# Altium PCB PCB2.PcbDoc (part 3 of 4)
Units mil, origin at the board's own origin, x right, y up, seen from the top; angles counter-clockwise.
Board outline 3980.79 x 2126 mil, 6 copper layers (Top Layer, Signal Layer 1, Signal Layer 2, Signal Layer 3, Signal Layer 4, Bottom Layer), stack 61.485 mil thick; 358 components, 190 nets, 1000 pads, 509 vias.
Unrouted connection lines stored in the file: 83.
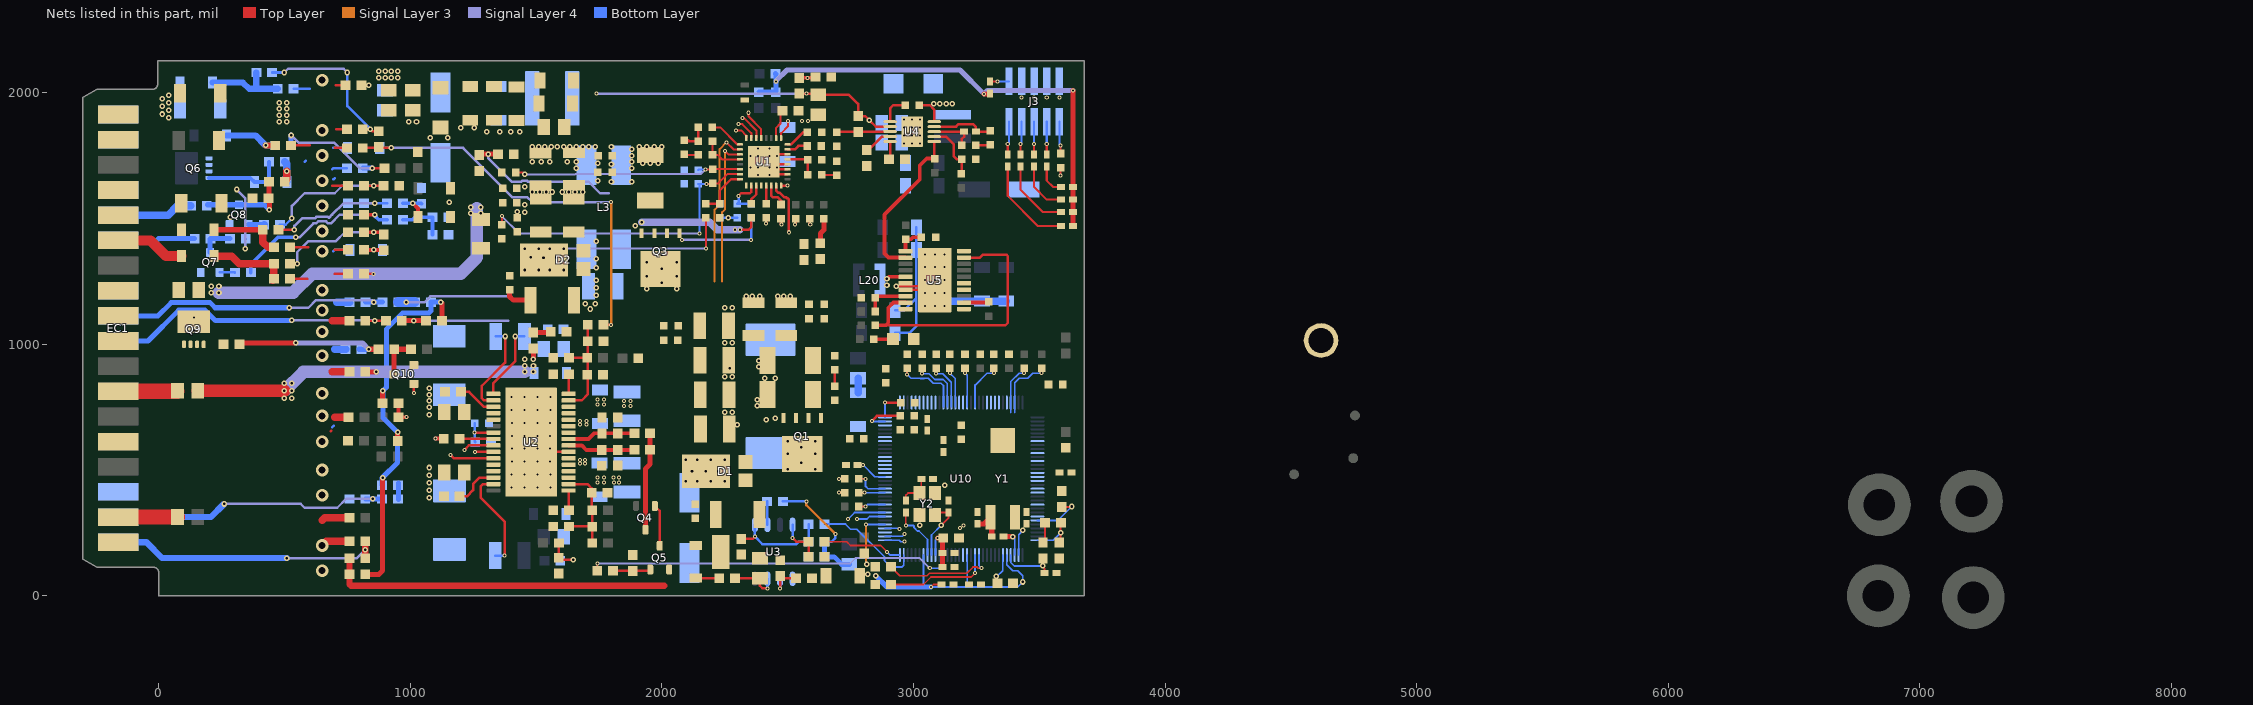
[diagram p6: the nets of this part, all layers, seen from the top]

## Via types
v1: diameter 22, hole 10, Top Layer to Bottom Layer, tented both sides, 287 vias
v2: diameter 16, hole 8, Top Layer to Bottom Layer, tented both sides, 129 vias
v3: diameter 19.68, hole 7.87, Top Layer to Bottom Layer, 47 vias
v4: diameter 19.68, hole 7.87, Top Layer to Bottom Layer, tented both sides, 28 vias
v5: diameter 50, hole 28, Top Layer to Bottom Layer, 18 vias

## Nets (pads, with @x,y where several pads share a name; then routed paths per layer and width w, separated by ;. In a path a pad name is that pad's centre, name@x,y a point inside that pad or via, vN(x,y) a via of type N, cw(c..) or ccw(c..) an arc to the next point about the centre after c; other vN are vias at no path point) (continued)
GND: C2.1 C3.1 C4.2 C5.2 C6.2 C7.2 C8.2 C9.2 C10.1 C11.2 C12.1 C13.1 C14.2 C15.1 C16.2 C17.2 C19.1 C20.2 C21.2 C22.2 C23.2 C24.2 C25.2 C26.2 C27.2 C28.2 C29.2 C31.2 C32.2 C34.1 C35.2 C36.2 C37.1 C38.1 C39.1 C40.2 C41.2 C42.2 C43.1 C44.2 C45.2 C46.2 C47.2 C48.2 C49.2 C51.2 C52.1 C53.1 C54.1 C55.2 C56.2 C57.2 C58.2 C59.2 C61.1 C62.2 C63.1 C64.2 C65.2 C66.2 C67.1 C68.2 C69.2 C70.2 C71.2 C72.2 C73.2 C74.2 C75.2 C76.2 C77.2 C78.2 C79.2 C80.2 C81.1 C82.2 C83.2 C85.2 C86.2 C87.2 C88.2 C89.2 C90.2 C92.2 C93.2 C94.2 C95.2 C96.2 C97.2 C98.2 C99.2 C100.2 C101.2 C102.2 C103.2 C104.2 C105.2 C106.2 C107.2 C108.2 C109.2 C110.2 C111.2 C112.2 C113.2 C114.2 C115.2 C116.2 C117.2 C118.2 C119.2 C120.2 C121.2 C122.2 C123.2 C124.2 C125.2 C126.2 C127.2 C128.2 C129.2 C130.2 C131.2 C132.2 C133.2 C134.2 D3.2 D4.2 D5.1 D8.2 D9.2 D10.2 D11.2 D15.2 D16.2 EC1.3 EC1.4 EC1.7 EC1.8 EC1.19 EC1.27 EC1.32 EC1.35 J3.3 J3.5 J3.7 J3.9 L3.2 Q5.2 Q7.2 Q8.2 Q9.1 Q9.2 Q9.3 Q10.2 R6.1 R7.1 R9.1 R10.1 R13.1 R23.1 R24.1 R29.1 R31.1 R32.1 R37.1 R39.1 R41.1 R47.1 R50.1 R53.1 R57.1 R58.1 R59.1 R60.1 R72.1 R76.1 R77.1 R78.1 R98.2 R101.2 R115.1 R116.1 R117.1 R118.1 RT1.1 TP3.1 U1.17 U1.20 U1.24 U1.26 U1.27 U1.28 U1.30 U1.33 U2.3 U2.4 U2.7 U2.10 U2.13 U2.14 U2.33@1480.2,610.59 U3.5 U4.9 U4.11@2995,1845 U5.6 U5.7 U5.10 U5.11 U5.14 U5.15 U5.20 U5.21@3085,1255 U10.10 U10.17 U10.48 U10.55 U10.58 U10.80 U10.114 Y1.3 Y2.2 Y2.4 | length 3402.6
  Top Layer w10: R59.1@521.5,1260 590,1260 ; R117.1@525,1385 595,1385 ; R115.1@526.5,1790 600,1790 ; 685,655 686.61,656.61 ; 690,1630 C49.2@753.5,1630 ; 700,1280 C134.2@753.5,1280 ; 700,1375 R60.1@753.5,1375 ; 700,1780 R58.1@748.5,1780 ; 705,2030 C68.2@743.5,2030 ; 705.35,1855 C17.2@748.5,1855 ; U2.33@1480.2,610.59 1539.41,610.59 1577.8,572.2 U2.7@1629.8,572.2 ; C41.2@2088.5,1810.24 2104.2,1810.24 2107.2,1807.24 C40.2@2145.5,1807.24 2145.5,1860.82 R24.1@2144.08,1862.24 ; U1.33@2405,1725 v3(2427.24,1747.24) 2434.53,1754.53 U1.30@2499.49,1754.53 ; U1.33@2414.84,1715.16 U1.28@2499.49,1715.16 ; v2@2416,1481 C39.1@2416,1503 ; U1.33@2434.53,1695.47 U1.27@2499.49,1695.47 ; U1.33@2454.21,1675.79 U1.26@2499.49,1675.79 ; U1.24@2473.9,1630.51 2499.49,1630.51 v2(2500,1630) ; v2(2530,1475) 2531.76,1476.76 C13.1@2531.76,1499.24 ; v2@2587.76,1477.24 R10.1@2587.76,1499.24 ; v1(2931.46,1230) U5.21@3060,1230 ; U5.7@2968.86,1216.61 3046.61,1216.61 U5.21@3060,1230 ; U4.9@3082.6,1864.69 3169.69,1864.69 3180,1875 3236.65,1875 3248.62,1863.03 C102.2@3248.62,1845 3302,1845 C104.2@3305,1848 ; v3(3085,1255) U5.21@3060,1230
  Top Layer w30: v5(650,200) 666.85,216.85 C88.2@758.5,216.85 ; 650,300 660,310 C133.2@758.5,310 ; 690,890 C86.2@758.5,890 ; 690.47,1093.7 C85.2@758.5,1093.7 ; 700,710 C57.2@755,710
  Bottom Layer w10: R57.1@536.5,2015 600,2015 ; 580,1725 585,1730 ; 690,670 695.31,675.31 ; 690,1695 695,1700 C31.2@748.5,1700 ; 695,1370 700,1375 D9.2@760.53,1375 ; 695,1655 699.43,1659.43 ; 695,1780 D8.2@749.96,1780 ; C34.1@2230,1502 C37.1@2300,1502 ; C95.2@2926.93,1045 2985,1045 3011.93,1071.93 3011.93,1183.8 ; C94.2@2926.93,1135 2963.13,1135 3011.93,1183.8 ; C89.2@3011.93,1465 C90.2@3011.93,1375 3011.93,1183.8
  Bottom Layer w30: 700,980 C66.2@743.5,980 ; 707.27,1167.27 C74.2@759.5,1167.27 ; v4(3124.37,1152.64) 3143.13,1171.39 C100.2@3273.21,1171.39 C101.2@3369.21,1171.39
  other v1: 3025,280 3125,440 2300,680 2250,730 2280,730 2380,755 2380,780 2410,865 2450,865 2250,870 2280,870 2270,905 2385,910 2385,935 2250,1005 2280,1005 2250,1145 2280,1145 2265,1502 285,1505 1455,1525 1425,1527.17 1455,1555 1155,1565 1485,1605 1515,1605 1540,1605 1565,1605 1605,1605 1630,1605 1655,1605 1685,1605 1455,1625 1800,1645 1880,1645 1880,1700 1800,1715 1925,1720 1955,1720 1985,1720 1880,1725 1880,1750 1880,1775 1800,1784.53 1910,1785 1940,1785 1970,1785 2000,1785 1080,1820 1150,1820 1435.46,1843.92 1305,1845 1355,1845 1400,1845 1200,1860 1255,1860 995,1885 1025,1885
  other v2: 3185,270 3200,280 1745,450 1770,450 1810,450 1830,450 1745,470 1770,470 1808.87,469.77 1830,470 1850,755 1875,755 1745,760 1770,760 1850,775 1875,775 1745,780 1770,780 2590,1475 2415,1480 3430,1980 3480,1980 3530,1980 3580,1980
  other v3: 1405.39,533.82 1454.61,533.82 1505.79,533.82 1555,533.82 1405.39,585 1454.61,585 1505.79,585 1555,585 1405.39,636.18 1454.61,636.18 1505.79,636.18 1555,636.18 1405.39,687.36 1454.61,687.36 1505.79,687.36 1555,687.36 3045.63,1203.82 3085,1203.82 3124.37,1203.82 3045.63,1255 3124.37,1255 3045.63,1306.18 3085,1306.18 3124.37,1306.18 2382.76,1671.85 2427.24,1671.85 2351.85,1702.76 2382.76,1702.76 2427.24,1702.76 2458.15,1702.76 2351.85,1747.24 2382.76,1747.24 2458.15,1747.24 2382.76,1778.15 2427.24,1778.15 2963.5,1829.25 2995,1829.25 3026.5,1829.25 2963.5,1860.75 2995,1860.75 3026.5,1860.75
  other v4: 1403.43,431.46 1454.61,431.46 1505.79,431.46 1556.97,431.46 1403.43,482.64 1454.61,482.64 1505.79,482.64 1556.97,482.64 1403.43,738.54 1454.61,738.54 1505.79,738.54 1556.97,738.54 1403.43,789.72 1454.61,789.72 1505.79,789.72 1556.97,789.72 3045.63,1152.64 3085,1152.64 3045.63,1357.36 3085,1357.36 3124.37,1357.36 2963.5,1797.76 2995,1797.76 3026.5,1797.76 2963.5,1892.24 2995,1892.24 3026.5,1892.24
  other v5: 650,100 650,400 650,500 650,612.99 650,715 650,805 650,955 650,1050 650,1135 650,1215 650,1370 650,1450 650,1550 650,1650 650,1750 650,1850 650,2050
HB: D7.2 EC1.11 | length 276.9
  Top Layer w40: EC1.11@-160.24,1412.99 -32.99,1412.99 30,1350 D7.2@90.53,1350
HB_DRIVE_MICRO: Q10.1 U10.49 | length 37.9
  Top Layer w10: Q10.1@1014.37,842.6 v2(1014.37,805.63) v2@1015,805
HB_LED: EC1.17 Q9.5 Q9.6 Q9.7 Q9.8 Q9.9@140,1089.33
  other v3: 140,1055.08 140,1105.28
HB_MICRO: D9.1 R56.2 R60.2 U10.103 | length 229.7
  Top Layer w15: R60.2@816.5,1375 v1(855,1375) 893.5,1375 R56.2@895,1373.5
  Bottom Layer w7: v2(2775,305) 2815,305 2825.39,315.39 U10.103@2886.85,315.39
  Bottom Layer w15: v1(855,1375) D9.1@889.47,1375
JTAG_TCK: R82.1 R86.2 U10.100 | length 349.5
  Top Layer w8: R86.2@3425,1706.38 3425,1615 3515,1525 R82.1@3586.38,1525
  Bottom Layer w7: U10.100@2886.85,268.15 2941.85,268.15 v2(2945,265)
JTAG_TDI: R84.1 R88.2 U10.98 | length 204.7
  Top Layer w8: R88.2@3530,1706.38 3530,1650 3555,1625 R84.1@3586.38,1625
  Bottom Layer w7: U10.98@2886.85,236.65 2956.65,236.65 v2(2965,245)
JTAG_TDO: R83.1 R87.2 U10.97 | length 289.1
  Top Layer w8: R87.2@3480,1706.38 3480,1625 3530,1575 R83.1@3586.38,1575
  Bottom Layer w7: U10.97@2886.85,220.91 2944.09,220.91 2950,215 v2(2965,215)
JTAG_TMS: R81.1 R85.2 U10.99 | length 377.5
  Top Layer w8: R85.2@3375,1706.38 3375,1590 3495,1470 R81.1@3586.38,1470
LB1/LB2: D6.2 D19.2 D20.2 EC1.1 EC1.2
  other v1: 40,1900 15,1915 40,1930 15,1945 40,1960 15,1975 40,1990
LB_FAULT: EC1.10 R127.1 | length 304.1
  Bottom Layer w30: EC1.10@-160.24,1512.99 37.99,1512.99 75,1550 R127.1@128.5,1550
LB_FAULT_MICRO: R129.2 U10.5
LB_MICRO: D8.1 R28.1 R54.2 R58.2 U10.118 | length 1637.8
  Top Layer w10: R58.2@811.5,1780 R54.2@871.5,1780 ; R54.2@875,1783.5 878.5,1780 v1(925,1780) ; R28.1@1768.5,1076.77 v2(1798.23,1076.77)
  Signal Layer 3 w10: v2(1798.23,1076.77) v2(1798.23,1565)
  Signal Layer 4 w10: v1(925,1780) 1210,1780 1405,1585 1465,1585 1485,1565 v2(1798.23,1565)
  Bottom Layer w10: D8.1@878.9,1780 v1(925,1780)
LB_NTC: C124.1 R136.1 R139.2 U10.18 | length 626.3
  Top Layer w10: v2(3205,885) C124.1@3205,905
  Top Layer w20: R139.2@966.5,1093.7 v1(1015,1093.7) R136.1@1060.57,1093.7
  Signal Layer 4 w10: v1(1015,1093.7) 1388.7,1093.7
  Bottom Layer w7: v2(3205,885) 3213.62,876.38 U10.18@3213.62,750
LBHB+: C63.2 C64.1 C86.1 D4.1 L2.1 R40.2 R52.1 U2.17 | length 1718.9
  Top Layer w10: U2.17@1330.59,802.52 1330.59,845.59 1416.68,931.68 v1(1416.68,1030.77)
  Top Layer w20: C86.1@821.5,890 v1(865,890) ; v1(1489.52,940.48) R40.2@1489.52,983.5
  Top Layer w50: L2.1@155,815 v1(500,815)
  Signal Layer 4 w50: v1(500,815) 575,890 v1(1455,890)
  Bottom Layer w10: v1(1416.68,1030.77) R52.1@1454.09,1030.77
  other v1: 500,785 530,785 530,815 500,845 530,845 1490,890 1455,915 1490,915 1455,940
LBHB-: EC1.16
LBHB_NTC: C85.1 EC1.20 R139.1 | length 1169.9
  Top Layer w10: C85.1@821.5,1093.7 v1(860,1093.7) R139.1@903.5,1093.7
  Signal Layer 4 w10: v1(529.58,1094.58) 859.12,1094.58 v1(860,1093.7)
  Bottom Layer w20: EC1.20@-160.24,1012.99 -42.01,1012.99 80,1135 185,1135 225.42,1094.58 v1(529.58,1094.58)
LBHB_RBIN: C74.1 EC1.18 R138.1 | length 1128.7
  Signal Layer 4 w10: v1(520,1145) 595,1145 625,1175 848.27,1175 v1(856,1167.27)
  Bottom Layer w20: EC1.18@-160.24,1112.99 -2.01,1112.99 50,1165 205,1165 225,1145 v1(520,1145) ; C74.1@822.5,1167.27 v1(856,1167.27) R138.1@889.5,1167.27
LBHBPWM: R51.1 U10.44
LHI_1-2: C58.1 R47.2 U2.23 | length 150.2
  Top Layer w10: v2(1256.02,648.98) U2.23@1330.59,648.98
  Bottom Layer w10: R47.2@1257.2,685.59 1257.2,612.09 C58.1@1258.7,610.59
LIN_RXD: R64.1 U10.95 | length 437.3
  Bottom Layer w7: R64.1@2646.5,285 2730,285 2750,265 2775,265 2885,155 2885,140 2910,115 2955,115 2961.65,121.65 U10.95@2961.65,161.85
LIN_TXD: R100.1 U10.96 | length 321.4
  Top Layer w7: R100.1@2646.5,215 2735,215 2750,200 2870,200 v2(2895,175)
  Bottom Layer w7: v2(2895,175) 2908.15,161.85 U10.96@2945.91,161.85
MCU_3V3A: C109.1 C114.1 L23.2 U10.8 | length 58.1
  Bottom Layer w30: C114.1@2780,806.93 L23.2@2780,865
MCU_3V3D: C105.1 C106.1 C107.1 C108.1 C110.1 L22.2 R16.2 R17.2 R20.2 R61.2 R62.2 R66.1 R80.2 R81.2 R82.2 R83.2 R84.2 R93.2 R94.1 R96.1 R99.1 R102.2 R103.2 R105.2 R130.2 R131.2 R135.2 R136.2 R140.2 R141.2 U10.7 U10.16 U10.26 U10.28 U10.39 U10.47 U10.51 U10.52 U10.69 U10.79 U10.90 U10.101 U10.113 U10.122 | length 5435.9
  Top Layer w7: C105.1@2778.62,520 v2(2800,520) ; v2(3070,35) 3080,45 C108.1@3111.38,45
  Top Layer w20: R141.2@821.5,85 875,85 890.16,100.16 v1(890.16,470) ; R130.2@890,765 v1@890,813.5 ; R131.2@950,615.94 v1(950,649.45) ; v1(1122.27,1167.27) 1126.5,1163.04 R136.2@1126.5,1093.7 ; v2(3280,1995) R80.2@3303.62,1995 ; R81.2@3633.62,1470 R82.2@3633.62,1525 R83.2@3633.62,1575 R84.2@3633.62,1625 v2(3633.62,2008.62)
  Signal Layer 3 w7: v2(2811.1,283.9) 2811.1,128.9 v1(2815,125)
  Signal Layer 3 w10: v2(2575,375) 2575,360 v2(2690,245)
  Signal Layer 4 w20: v2(2453,2045) 2498,2090 3185,2090 v2(3280,1995) 3293.62,2008.62 v2(3633.62,2008.62)
  Bottom Layer w7: v2(2800,520) 2847.13,472.87 U10.113@2886.85,472.87 ; v2(2811.1,283.9) U10.101@2886.85,283.9 ; U10.90@3040.39,161.85 3040.39,45.39 3050.79,35 ; v2(3070,35) 3213.62,35 ; U10.79@3213.62,161.85 3213.62,35 ; U10.69@3371.1,161.85 3371.1,124.1 3395.2,100 3415,100 3435,80 v1(3435,55) 3415,35 3213.62,35
  Bottom Layer w10: R66.1@2481.5,375 v2(2575,375) ; R62.2@2646.5,215 2675,215 2690,230 v2(2690,245)
  Bottom Layer w20: R140.2@888.5,440 v1@888.5,468.35 ; v1(890.16,470) 950,529.84 v1(950,649.45) 891.5,707.95 v1(891.5,815) 905,828.5 905,1060 970,1125 1075,1125 1082.5,1132.5 R135.2@1082.5,1167.27 v1(1122.27,1167.27) ; R17.2@2386,2001.5 R16.2@2453,2001.5 v2(2453,2045) 2453,2073.5 R20.2@2451.5,2075 ; R62.2@2646.5,215 R61.2@2646.5,155 2685,155 2715,125 L22.2@2745,125 ; v1(2850,80) 2895,35 3050.79,35 v2(3070,35)
  other v1: 2818.98,86.46
MISOM: R93.1 U1.7 U2.26 U10.1 | length 158.7
  Top Layer w8: v2(2305,1875) 2320,1875 2355.79,1839.21 U1.7@2355.79,1819.49
  Top Layer w10: v2(1257.2,572.2) U2.26@1330.59,572.2
MOSIM: U1.8 U2.27 U10.2 | length 235.4
  Top Layer w8: v2(2295,1850) 2315,1850 2336.1,1828.9 U1.8@2336.1,1819.49
  Top Layer w10: v2(1160,560) 1173.39,546.61 U2.27@1330.59,546.61
NetC1_1: C1.1 R1.1
NetC12_2: C12.2 R4.1 U1.23 | length 280.3
  Top Layer w10: U1.23@2454.21,1630.51 2454.21,1610.79 2462.13,1602.87 2467.4,1602.87 2487.07,1583.2 2494.06,1583.2 2497.27,1580 2500,1580 2503.88,1576.12 2503.88,1446.12 v2(2505,1445) ; R4.1@2687,832.68 C12.2@2687,897.68
NetC14_1: C14.1 R12.2 | length 59.2
  Top Layer w8: R12.2@2636.2,1672.94 2694.06,1672.94 C14.1@2695,1672
NetC15_2: C15.2 R12.1 U1.29 | length 141.5
  Top Layer w10: U1.29@2499.49,1734.84 2578.3,1734.84 C15.2@2580.2,1732.94 R12.1@2580.2,1672.94
NetC16_1: C16.1 R11.2 R14.2 U1.1 | length 79.3
  Top Layer w8: U1.1@2473.9,1819.49 2473.9,1839.29 2501.85,1867.24 v2(2501.85,1887.24)
  other v2: 2556.85,1887.24 2581.85,1887.24
NetC17_1: C17.1 R44.2 R54.1 | length 640.8
  Top Layer w10: C17.1@811.5,1855 v1(841.46,1855) 849.96,1846.5 R54.1@875,1846.5
  Signal Layer 4 w10: v1(500,2080) 515,2095 735,2095 v1(750,2080)
  Bottom Layer w10: R44.2@451.5,2080 v1(500,2080) ; v1(750,2080) 750,1946.46 v1(841.46,1855)
NetC18_1: C18.1 R18.1 | length 116.6
  Top Layer w20: C18.1@1395,1217 1395,1190 1410,1175 R18.1@1478.39,1175
NetC18_2: C18.2 C25.1 C26.1 C27.1 D2.3 R19.1 R22.2 R26.2 | length 687
  Top Layer w8: v2(2175,1380) R22.2@2175,1502
  Signal Layer 4 w8: v1(1610,1380) v2(2175,1380)
  other v1: 1455,1295 1510,1295 1555,1295 1610,1295 1529.76,1343.76 1480,1345 1580,1345 1455,1380 1510,1380 1555,1380
NetC24_1: C24.1 R55.2 R56.1 | length 494.3
  Top Layer w10: R55.2@521.5,1320 v1(551.02,1320)
  Top Layer w15: C24.1@816.5,1445 v1(855,1445) 886.5,1445 R56.1@895,1436.5
  Signal Layer 4 w10: v1(551.02,1320) 551.02,1366.02 595,1410 705,1410 740,1445 v1(855,1445)
NetC30_1: C30.1 L3.3 Q3.5
  other v1: 1940,1220 2060,1220 2000,1245 1940,1270 2060,1270 2000,1300 1940,1325 2060,1325 2000,1355
NetC30_2: C30.2 D2.1 D2.2 L3.4 R18.2
  other v1: 1715,1140 1695,1160 1735,1160 1740,1195 1740,1225 1740,1255 1740,1304.22 1740,1340 1740,1410
NetC31_1: C31.1 R111.2 R112.1 | length 510.3
  Top Layer w10: v1(850,1700) R112.1@898.5,1700
  Signal Layer 4 w10: v1(526.5,1830.99) 557.49,1800 698.98,1800 798.98,1700 v1(850,1700)
  Signal Layer 4 w20: v1@526.5,1826.5 v1(526.5,1830.99)
  Bottom Layer w20: R111.2@526.5,1790 v1(526.5,1830.99) ; C31.1@811.5,1700 v1(850,1700)
NetC32_1: C32.1 R113.2 R114.1 | length 530.4
  Top Layer w10: R113.2@477.07,1455 v1(540,1455)
  Signal Layer 4 w10: v1(540,1455) 540,1470 570,1500 621.16,1500 626.91,1505.75 673.09,1505.75 676.92,1501.92 690,1515 735,1560 v1(860,1560)
  Bottom Layer w10: C32.1@816.5,1560 v1(860,1560) R114.1@908.5,1560
NetC33_1: C33.1 C35.1 R26.1 U1.15 | length 1228.9
  Top Layer w8: R26.1@1364.15,1475.76 v2(1364.15,1509.15) ; v2(2176.85,1637.24) 2199.85,1637.24 C33.1@2201.85,1639.24 2223.85,1639.24 2260.39,1675.79 U1.15@2310.51,1675.79
  Signal Layer 4 w8: v2(1364.15,1509.15) 1433.3,1440 v2(2150,1440)
  Bottom Layer w8: v2(2150,1440) 2150,1632.09 C35.1@2144.85,1637.24 v2(2176.85,1637.24)
NetC33_2: C33.2 C36.1 R27.1 U1.14 | length 932.1
  Top Layer w8: R27.1@1420.2,1682.44 1447.56,1682.44 v1(1455,1675) ; v2(2173.85,1695.24) C33.2@2201.85,1695.24 2202.08,1695.47 U1.14@2310.51,1695.47
  Signal Layer 4 w8: v1(1455,1675) 1655,1675 1657.13,1677.13 2155.73,1677.13 v2(2173.85,1695.24)
  Bottom Layer w8: C36.1@2144.85,1692.24 2147.85,1695.24 v2(2173.85,1695.24)
NetC34_2: C34.2 R22.1 R29.2 U1.16 | length 206.6
  Top Layer w10: R22.1@2175,1558 R29.2@2230,1558 2230,1610 2276.1,1656.1 U1.16@2310.51,1656.1
NetC37_2: C37.2 R30.1 U1.18 | length 171.1
  Top Layer w10: v2(2305,1590) 2315,1600 2350,1600 2355.79,1605.79 U1.18@2355.79,1630.51
  Bottom Layer w10: v2(2305,1590) 2305,1563 C37.2@2300,1558 R30.1@2355,1558
NetC39_2: C39.2 U1.21 | length 72
  Top Layer w10: U1.21@2414.84,1630.51 2414.84,1560.16 C39.2@2416,1559
NetC40_1: C40.1 R33.2 U1.12 | length 171.2
  Top Layer w8: C40.1@2201.5,1807.24 R33.2@2201.5,1752.24 2221.85,1752.24 2239.25,1734.84 U1.12@2310.51,1734.84
NetC41_1: C41.1 R33.1 | length 57.8
  Top Layer w8: C41.1@2088.5,1754.24 2090.5,1752.24 R33.1@2145.5,1752.24
NetC42_1: C42.1 R123.2 R124.1 | length 717
  Top Layer w15: C42.1@816.5,1515 v1(860,1515)
  Signal Layer 4 w10: v1(545,1425) 560,1425 615,1480 626.44,1480 634.31,1487.87 665.69,1487.87 673.56,1480 685,1480 720,1515 v1(860,1515)
  Bottom Layer w15: R123.2@366.5,1285 366.5,1316.5 475,1425 v1(545,1425) ; v1(860,1515) 860,1510 875,1495 R124.1@908.5,1495
NetC45_1: C45.1 R124.2 R125.1 | length 191.2
  Bottom Layer w15: R124.2@971.5,1495 1008.95,1495 1018.95,1505 C45.1@1088.5,1505 R125.1@1088.5,1435
NetC48_1: C48.1 U2.1 | length 78.9
  Top Layer w10: U2.1@1629.8,418.66 1629.8,342.48 C48.1@1631.69,340.59
NetC49_1: C49.1 R128.2 R129.1 | length 543.4
  Top Layer w10: C49.1@816.5,1630 v1(855,1630) R129.1@893.5,1630
  Signal Layer 4 w10: v1(530,1500) 530,1550 580,1600 700,1600 730,1630 v1(855,1630)
  Bottom Layer w10: R128.2@482.07,1475 505,1475 v1(530,1500)
NetC50_1: C50.1 L4.1 L5.2
  other v1: 1075,390 1075,420 1075,450 1075,480 1075,510
NetC50_2: C50.2 U2.30 | length 179.3
  Top Layer w10: C50.2@1196.69,395.59 1225.59,395.59 1250,420 1250,445 1274.84,469.84 U2.30@1330.59,469.84
NetC51_1: C51.1 R15.2 R34.1 R36.2 R37.2 U2.2 | length 408.5
  Top Layer w10: U2.2@1629.8,444.25 1703.9,444.25 1721.5,426.65 R37.2@1721.5,409.61 1721.5,342 R34.1@1723.5,340 R36.2@1723.5,275 ; C51.1@1631.69,275.59 1722.91,275.59 R36.2@1723.5,275 ; R15.2@1723.5,210 R36.2@1723.5,275
NetC53_2: C53.2 C54.2 R42.2 U2.8 | length 268.7
  Top Layer w15: U2.8@1629.8,597.8 1682.2,597.8 1699.91,580.09 C53.2@1761.56,580.09 1890.19,580.09 R42.2@1890.87,580.77
NetC55_1: C55.1 C56.1 R45.2 U2.9 | length 270.3
  Top Layer w15: U2.9@1629.8,623.39 1708.39,623.39 1730.77,645.77 R45.2@1890.87,645.77
NetC60_1: C60.1 L7.1 L8.2
  other v1: 1075,720 1075,750 1075,775 1075,800 1075,825
NetC60_2: C60.2 U2.19 | length 153.4
  Top Layer w10: C60.2@1201.69,810.59 1234.41,810.59 1293.66,751.34 U2.19@1330.59,751.34
NetC61_2: C61.2 R28.2 R49.1 R51.2 R53.2 U2.15 | length 434
  Top Layer w10: U2.15@1629.8,776.93 1681.93,776.93 1705.5,800.5 R51.2@1705.5,1011.77 R28.2@1705.5,1076.77 ; C61.2@1631.69,945.59 1702.32,945.59 R49.1@1703.5,946.77
NetC62_1: C62.1 U2.16 | length 78.9
  Top Layer w10: U2.16@1629.8,802.52 1629.8,878.7 C62.1@1631.69,880.59
NetC66_1: C66.1 R137.1 R144.2 | length 602.9
  Top Layer w20: R144.2@321.5,1000 326.5,1005 v1(545,1005) ; v1(835,980) R137.1@873.5,980
  Signal Layer 4 w20: v1(545,1005) 810,1005 v1(835,980)
  Bottom Layer w20: C66.1@796.5,980 v1(835,980)
NetC67_2: C67.2 R63.2 U3.7 | length 200.4
  Top Layer w10: R63.2@2291.5,70 C67.2@2390,70 2390,40 2400,30 v2(2420,30)
  Bottom Layer w10: v2(2420,30) U3.7@2420,67.72
NetC68_1: C68.1 C69.1 C70.1 C71.1 C72.1 C73.1 C75.1 C76.1 C77.1 D5.2 D12.1 D18.1 D19.1 D20.1 L10.1 Q6.1 Q6.2 Q6.3 R119.2 R120.2 | length 319.6
  Top Layer w10: C68.1@806.5,2030 v1(836.02,2030)
  Signal Layer 4 w10: v1(310,1615) 345,1580 v1(345,1380)
  Bottom Layer w10: v1(345,1380) 345,1418.5 R120.2@346.5,1420
  other v1: 480,1885 510,1885 480,1910 510,1910 480,1935 510,1935 480,1960 510,1960 875,2060 900,2060 925,2060 950,2060 875,2085 900,2085 925,2085 950,2085
NetC81_2: C81.2 R65.1 U3.6 | length 153.2
  Top Layer w10: v2(2470,30) R65.1@2470,78.5 2478.5,70 C81.2@2533.5,70
  Bottom Layer w10: v2(2470,30) U3.6@2470,67.72
NetC82_1: C82.1 R61.1 R100.2 U3.4 | length 182
  Top Layer w10: v2(2520,230) 2535,215 R100.2@2583.5,215 C82.1@2583.5,155
  Bottom Layer w10: v2(2520,230) U3.4@2520,282.28
NetC83_1: C83.1 R62.1 R64.2 U3.1 | length 405.9
  Top Layer w10: C83.1@2315,226.5 2361.5,226.5 v2(2370,235)
  Bottom Layer w10: U3.1@2370,282.28 v2(2370,235) 2400,205 2535,205 2545,215 R62.1@2583.5,215 R64.2@2583.5,285
NetC91_1: C91.1 U4.1 | length 117.8
  Top Layer w10: U4.1@2907.4,1884.37 2907.4,1937.4 2920,1950 C91.1@2967,1950
NetC91_2: C91.2 D11.1 L21.1 U4.10 | length 114.9
  Top Layer w10: C91.2@3023,1950 3065,1950 3082.6,1932.4 U4.10@3082.6,1884.37
  other v1: 3080,1955 3105,1955 3130,1955 3155,1955
NetC99_1: C99.1 R73.2 U5.1 | length 112.6
  Top Layer w15: U5.1@2968.86,1370.16 2968.86,1415.86 R73.2@2970,1417 2990.62,1417 2998.62,1425 C99.1@3032,1425
NetC102_1: C102.1 R74.2 U4.8 | length 177.7
  Top Layer w10: U4.8@3082.6,1845 C102.1@3201.38,1845 3201.38,1824.72 3192,1815.35 R74.2@3192,1790
NetC103_1: C103.1 U4.4 | length 119.7
  Top Layer w10: C103.1@2806.5,1780 2830,1780 2875.32,1825.32 U4.4@2907.4,1825.32
NetC104_1: C104.1 R74.1 | length 55
  Top Layer w10: R74.1@3248,1790 C104.1@3303,1790
NetC111_1: C111.1 C112.1 C113.1 U10.87 U10.115 | length 210.6
  Top Layer w20: v2(3095,230) C111.1@3118.5,230 3116.38,227.87 C112.1@3116.38,170 C113.1@3116.38,115
  Bottom Layer w7: U10.87@3087.64,161.85 3088.07,162.29 3088.07,223.07 v2(3095,230)
NetC115_1: C115.1 R95.2 U10.68 | length 224.5
  Top Layer w7: R95.2@3515,148.5 3515,115 3521.38,108.62 C115.1@3521.38,90
  Bottom Layer w7: U10.68@3386.85,161.85 3386.85,132.32 3400.63,118.54 v1@3515,118.54
  other v1: 3515,120
NetC120_1: C120.1 R104.2 Y1.2 | length 140.9
  Top Layer w20: C120.1@3255,286.38 3280.04,286.38 Y1.2@3305.79,312.13 3311.38,306.54 R104.2@3311.38,235
NetC121_1: C121.1 U10.66 Y1.1 | length 105
  Bottom Layer w7: U10.66@3418.35,161.85 3418.35,243.35 v1(3435,260)
NetC122_1: C122.1 R106.2 Y2.1 | length 138.3
  Top Layer w7: R106.2@2970,378.62 2970,400 2978.31,408.31 Y2.1@3023.5,408.31 3031.38,416.18 C122.1@3031.38,465
NetC123_1: C123.1 U10.88 Y2.3 | length 255.3
  Top Layer w7: Y2.3@3086.5,321.69 3096.18,331.38 C123.1@3140,331.38 3140,310 v1(3110,280)
  Bottom Layer w7: U10.88@3071.89,161.85 3071.89,241.89 v1(3110,280)
NetD1_1: D1.1 D1.2 L1.2 Q1.5 R1.2
  other v1: 2500,502.62 2610,502.62 2555,528.91 2500,565 2610,565 2555,590 2500,615 2610,615
NetD6_1: D6.1 R44.1 R57.2 | length 335.8
  Bottom Layer w25: D6.1@214.47,2040 335,2040 360,2015 385,2015 ; R44.1@388.5,2080 388.5,2018.5 385,2015 ; R57.2@473.5,2015 385,2015
NetD7_1: D7.1 R55.1 R59.2 | length 318.5
  Top Layer w30: D7.1@219.47,1350 290,1350 320,1320 R55.1@458.5,1320 R59.2@458.5,1260 R59.2@453.5,1255
NetD10_1: D10.1 R71.1 | length 75.7
  Top Layer w15: R71.1@2843,1020 D10.1@2918.66,1020
NetD13_1: D13.1 R111.1 R115.2 | length 249.1
  Top Layer w25: v1(425,1790) R115.2@463.5,1790
  Bottom Layer w25: D13.1@269.47,1830 385,1830 v1(425,1790) R111.1@463.5,1790
NetD14_1: D14.1 R113.1 R117.2 | length 296.8
  Top Layer w20: D14.1@219.47,1455 R113.1@414.07,1455
  Top Layer w30: R113.1@414.07,1455 414.08,1405.92 435,1385 R117.2@458.5,1385
NetD17_1: D17.1 Q6.4 R121.2 | length 323
  Bottom Layer w15: Q6.4@200.43,1661 364.53,1661 D17.1@380.53,1645 435.57,1645 438.5,1647.93 R121.2@438.5,1725
NetD17_2: D17.2 R121.1 R126.2 | length 116.5
  Top Layer w30: R126.2@509.47,1655 510,1655.53 v1(510,1687.5)
  Bottom Layer w30: R121.1@501.5,1725 510,1716.5 v1(510,1687.5) 510,1645.53 D17.2@509.47,1645
NetD21_1: D21.1 R63.1 | length 93.7
  Top Layer w10: D21.1@2135,70.53 2227.97,70.53 R63.1@2228.5,70
NetEC1_15: EC1.15 L9.2
NetEC1_23: EC1.23 L2.2 | length 233.2
  Top Layer w60: EC1.23@-160.24,812.99 L2.2@72.99,812.99
NetEC1_33: EC1.33 L6.2 | length 235.2
  Top Layer w60: EC1.33@-160.24,312.99 L6.2@75,312.99
NetJ3_1: J3.1 R80.1 | length 75.6
  Top Layer w8: R80.1@3305,2043.62 v2(3333.62,2043.62)
  Bottom Layer w8: v2(3333.62,2043.62) 3378.5,2043.62 J3.1@3380,2045.12
NetJ3_2: J3.2 R85.1 | length 133.3
  Top Layer w8: R85.1@3375,1753.62 v2(3375,1795)
  Bottom Layer w8: v2(3375,1795) 3380,1800 J3.2@3380,1884.88
NetJ3_4: J3.4 R86.1 | length 133.3
  Top Layer w8: R86.1@3425,1753.62 v2(3425,1795)
  Bottom Layer w8: v2(3425,1795) 3430,1800 J3.4@3430,1884.88
NetJ3_6: J3.6 R87.1 | length 131.3
  Top Layer w8: R87.1@3480,1753.62 v2(3480,1795)
  Bottom Layer w8: v2(3480,1795) J3.6@3480,1884.88
NetJ3_8: J3.8 R88.1 | length 131.3
  Top Layer w8: R88.1@3530,1753.62 v2(3530,1795)
  Bottom Layer w8: v2(3530,1795) J3.8@3530,1884.88
NetJ3_10: J3.10 R89.1 | length 129
  Top Layer w8: R89.1@3585,1758 v2(3585,1790)
  Bottom Layer w8: J3.10@3580,1884.88 3580,1795 v2(3585,1790)
NetL4_2: L4.2 R35.1 U2.31 | length 406.1
  Top Layer w10: U2.31@1330.59,444.25 1289.64,444.25 1280,434.62 1280,390 1375.32,294.68 v2(1375.32,160)
  Bottom Layer w10: R35.1@1337.91,160 v2(1375.32,160)
NetL5_1: L5.1 U2.28 U2.29
NetL7_2: L7.2 R52.2 U2.18 | length 370.2
  Top Layer w10: U2.18@1330.59,776.93 1293.35,776.93 1285,785.28 1285,835 1377.31,927.31 v1(1377.31,1030.77)
  Bottom Layer w10: R52.2@1339.91,1030.77 v1(1377.31,1030.77)
NetL8_1: L8.1 U2.20 U2.21
NetL20_1: L20.1 U5.5 | length 66.1
  Top Layer w15: 2902.8,1267.8 U5.5@2968.86,1267.8
  other v1: 2895,1235 2895,1260
NetQ1_1: Q1.1 Q1.2 Q1.3 R4.2 R6.2 R9.2
NetQ1_4: Q1.4 R2.2 | length 24.9
  Top Layer w10: R2.2@2473.73,1499.33 2473.73,1476.27 v2(2475,1475)
  other v1: 2415,700 2450,705
NetQ3_1: Q3.1 Q3.2 Q3.3 R30.2 R32.2 | length 362
  Signal Layer 4 w10: v2(2080,1415) v2(2355,1415)
  Bottom Layer w10: v2(2355,1415) R30.2@2355,1502
NetQ3_4: Q3.4 R25.2 | length 488.6
  Top Layer w10: v2(2310,1455) 2345,1455 2355,1465 R25.2@2355,1502
  Signal Layer 4 w30: v1(1920,1485) 2190,1485 2220,1455 v2(2310,1455)
  other v1: 1895,1470
  other v2: 2290,1455
NetQ4_1: Q4.1 Q5.3 R46.1 | length 166.3
  Top Layer w10: Q4.1@1972.4,357.24 1991.7,337.95 Q5.3@1991.7,198.94
NetQ4_3: Q4.3 R42.1 R45.1 | length 390.8
  Top Layer w20: Q4.3@1935,262.76 1935,505 1953.86,523.86 R42.1@1953.86,580.77 R45.1@1953.86,645.77
NetQ5_1: Q5.1 R48.1 R50.2 | length 149.6
  Top Layer w10: R48.1@1806.5,100 1949.84,100 Q5.1@1954.3,104.45
NetQ7_1: Q7.1 R123.1 | length 61.4
  Bottom Layer w10: Q7.1@242.4,1285.63 302.87,1285.63 R123.1@303.5,1285
NetQ7_3: Q7.3 R120.1 R122.2 | length 131.1
  Bottom Layer w20: Q7.3@205,1364.37 R122.2@205,1418.5 ; R122.2@206.5,1420 R120.1@283.5,1420
NetQ8_1: Q8.1 R128.1 | length 64.7
  Bottom Layer w20: Q8.1@357.4,1475.63 R128.1@418.45,1475.63
  Bottom Layer w30: R128.1@416.48,1472.4 R128.1@419.07,1475
NetQ8_3: Q8.3 R119.1 R126.1 R127.2 | length 365
  Top Layer w20: R119.1@436.5,1580 440,1576.5 v1(440,1535) ; R119.1@438.5,1580 R126.1@438.5,1645
  Bottom Layer w20: R127.2@194.45,1554.37 Q8.3@320,1554.37 420.63,1554.37 v1(440,1535)
NetQ9_4: Q9.4 R144.1
NetQ10_3: Q10.3 R134.1 R137.2 | length 167.6
  Top Layer w20: Q10.3@935,880 935,978.5 R137.2@936.5,980 R134.1@1003.5,980
NetR2_1: R2.1 U1.22 | length 103.1
  Top Layer w10: U1.22@2434.53,1630.51 2434.53,1590.47 2440,1585 2460,1585 2473.73,1571.27 R2.1@2473.73,1555.33
NetR14_1: R14.1 U1.2 | length 118.6
  Top Layer w8: U1.2@2454.21,1819.49 2454.21,1859.61 2471.85,1877.24 2471.85,1918.74 R14.1@2480.35,1927.24
NetR24_2: R24.2 U1.9 | length 138.7
  Top Layer w8: R24.2@2200.08,1862.24 2231.85,1862.24 2300.2,1793.9 U1.9@2310.51,1793.9
NetR25_1: R25.1 U1.19 | length 81
  Top Layer w10: R25.1@2355,1558 2355,1575 2375.47,1595.47 U1.19@2375.47,1630.51
NetR31_2: R31.2 U1.32 | length 99.4
  Top Layer w10: U1.32@2499.49,1793.9 2513.5,1793.9 2561.85,1842.24 R31.2@2578.85,1842.24
NetR43_1: R43.1 U2.24 | length 140.3
  Top Layer w10: R43.1@1193.05,630 1199.66,623.39 U2.24@1330.59,623.39
NetR65_2: R65.2 TP1.1
NetR66_2: R66.2 U3.2 | length 93.3
  Bottom Layer w10: R66.2@2418.5,375 2420,373.5 U3.2@2420,282.28
NetR67_1: R67.1 U4.6 U5.2 | length 638.5
  Top Layer w10: U4.6@3082.6,1805.63 3082.6,1740.4 R67.1@3085,1738
  Top Layer w15: U5.2@2968.86,1344.57 2900.43,1344.57 2885,1360 2885,1515 3025,1655 3025,1710 3053,1738 R67.1@3085,1738
NetR68_1: R68.1 R76.2 U4.3 | length 212.4
  Top Layer w10: R76.2@2695,1845 U4.3@2907.4,1845
NetR69_2: R69.2 R72.2 U5.8 | length 172.2
  Top Layer w15: R72.2@2848,1185 R69.2@2848,1130 R69.2@2850,1128 ; R72.2@2854.45,1191.02 U5.8@2968.86,1191.02
NetR70_1: R70.1 U5.9 U5.19 | length 1169.9
  Top Layer w10: R70.1@2848,1075 3365,1075 3375,1085 3375,1350 3370,1355 3275,1355 3264.57,1344.57 U5.19@3201.14,1344.57
  Top Layer w15: R70.1@2848,1075 2890,1075 2900,1085 2900,1145 2920.43,1165.43 U5.9@2968.86,1165.43
NetR75_1: R75.1 R77.2 U4.7 | length 232.3
  Top Layer w10: U4.7@3082.6,1825.32 3129.68,1825.32 3160,1795 3160,1747.83 3172.83,1735 R77.2@3192,1735 3192,1680 R75.1@3190,1678
NetR78_2: R78.2 U4.5 | length 66.7
  Top Layer w10: R78.2@2907.4,1738.9 U4.5@2907.4,1805.63
NetR79_1: R79.1 U5.12 | length 99.9
  Top Layer w15: U5.12@3201.14,1165.43 3297.43,1165.43 R79.1@3300,1168
NetR92_1: R92.1 U10.42
NetR94_2: R94.2 U10.9
NetR95_1: R95.1 R96.2 R97.2 | length 82
  Top Layer w7: R95.1@3515,211.5 3523.5,220 R97.2@3523.5,290
NetR101_1: R101.1 U10.59 | length 200.4
  Top Layer w7: R101.1@3590,353.5 3628.5,353.5 v1(3630,355)
  Bottom Layer w7: U10.59@3493.15,299.65 3574.65,299.65 v1(3630,355)
NetR104_1: R104.1 U10.67 | length 112.7
  Top Layer w20: R104.1@3358.62,235 v1(3395,235)
  Bottom Layer w7: v1(3395,235) 3402.6,227.4 U10.67@3402.6,161.85
NetR106_1: R106.1 U10.89 | length 226.7
  Top Layer w7: v2(2970,280) R106.1@2970,331.38
  Bottom Layer w7: v2(2970,280) 3000,280 3002.63,277.37 3002.63,270.73 3015.73,257.63 3022.37,257.63 3056.14,223.86 U10.89@3056.14,161.85
PC4: U10.25
PC5: U10.24
PC6: U10.23
PD3: U1.6 U2.25 U10.4 | length 229.4
  Top Layer w8: v2(2320,1900) 2325,1900 2375.47,1849.53 U1.6@2375.47,1819.49
  Top Layer w10: v2(1215,580) 1232.8,597.8 U2.25@1330.59,597.8
PD5: C130.1 R135.1 R138.2 U10.126 | length 485.4
  Signal Layer 4 w10: v1(985,1167.27) 1057.8,1167.27 1080.53,1190 1111.24,1190 1112.38,1191.14 1132.15,1191.14 1133.29,1190 1395,1190
  Bottom Layer w40: R138.2@952.5,1167.27 v1(985,1167.27) R135.1@1017.5,1167.27
PD6: C129.1 R130.1 R132.2 U10.127 | length 259.8
  Top Layer w10: v2(2835,695) 2855,715 C129.1@2947,715
  Top Layer w15: R130.1@952.99,765 R132.2@952.99,710 v2(985,710)
  Bottom Layer w7: v2(2835,695) 2836.65,693.35 U10.127@2886.85,693.35
PD7: C128.1 R140.1 R142.2 U10.128 | length 186.6
  Top Layer w10: v2(2886.85,768.15) C128.1@2949.4,768.15
  Bottom Layer w7: U10.128@2886.85,709.09 v2(2886.85,768.15)
  Bottom Layer w20: R142.2@953.15,383.54 R140.1@953.15,448.54
PE0: C116.1 R40.1 R41.2 U10.15 | length 234.3
  Top Layer w7: v2(3145,885) C116.1@3145,905
  Top Layer w20: R40.1@1489.52,1046.5 1555,1046.5 R41.2@1558.5,1050
  Bottom Layer w7: v2(3145,885) 3166.38,863.62 U10.15@3166.38,750
PE1: C117.1 R38.1 R39.2 U10.14 | length 321.5
  Top Layer w7: v2(3090,883) C117.1@3090,905
  Top Layer w10: R38.1@1591.5,210 1590,208.5 1590,142.95 v1(1647.95,142.95)
  Bottom Layer w7: v2(3090,883) 3117,883 3150.63,849.37 U10.14@3150.63,750
PE2: C118.1 R21.1 R23.2 U10.13 | length 863.9
  Top Layer w7: v2(3035,883) C118.1@3035,904.45
  Top Layer w20: R21.1@1275,1751.5 1279.26,1755.76 v1(1310,1755.76) R23.2@1348.6,1755.76
  Signal Layer 4 w10: v1(1310,1755.76) 1310,1740 1405,1645 1441.24,1645 1445.11,1648.87 1464.89,1648.87 1468.76,1645 1710,1645 1755,1600 1790,1600
  Bottom Layer w7: v2(3035,883) 3062,883 3085,860 3118.96,860 3134.88,844.08 U10.13@3134.88,750
PE3: C131.1 R5.1 R7.2 U10.12 | length 339.4
  Top Layer w7: v2(2975,880.28) 2975,902.72 2974.13,903.58 C131.1@2975,904.45
  Top Layer w15: R5.1@2546.85,2058.74 2606.85,2058.74 R7.2@2610.35,2062.24
  Bottom Layer w7: v2(2975,880.28) 2990.28,865 3025.6,865 3026.98,863.63 3043.02,863.63 3044.4,865 3058.96,865 3078.84,845.13 3109.87,845.13 3119.13,835.87 U10.12@3119.13,750
  other v2: 2580,2058.74
PE4: C132.1 R8.1 R13.2 U10.123
PH0: R91.1 U10.29 | length 210.6
  Top Layer w10: v2(3440,885) R91.1@3440,905
  Bottom Layer w7: 3386.85,728.15 3386.85,851.85 3420,885 v2(3440,885)
PH1: U10.30 | length 261.7
  Top Layer w10: v2(3510,885) 3510,905
  Bottom Layer w7: 3402.6,728.15 3402.6,846.56 3421.03,865 3455,865 3475,885 v2(3510,885)
PJ0: U10.116
PJ1: U10.117
PL4: R48.2 U10.85 | length 1476.9
  Top Layer w7: R48.2@1743.5,100 v2(1743.5,128.5)
  Signal Layer 4 w7: v2(1743.5,128.5) 2748.5,128.5 2770,150 3025,150 v2(3065,110)
  Bottom Layer w7: v2(3065,110) 3111.38,110 3119.13,117.76 U10.85@3119.13,161.85
PM1: R102.1 U1.11 U10.77 | length 1010.1
  Top Layer w7: R102.1@2911.5,45 3040,45 3070,75 3230,75 v2(3245,90)
  Top Layer w8: v2(2251.85,1767.24) 2264.57,1754.53 U1.11@2310.51,1754.53
  Signal Layer 3 w8: 2240,1250 2240,1525 2251.85,1536.85 v2(2251.85,1767.24)
  Bottom Layer w7: v2(3245,90) 3245,161.73 U10.77@3245.12,161.85
PM2: R103.1 U1.10 U10.76 | length 1081.6
  Top Layer w7: R103.1@2911.5,115 2946.5,80 3053.96,80 3063.84,89.87 3212.59,89.87 3237.09,114.37 3253.14,114.37 3257.52,110 v2(3270,110)
  Top Layer w8: v2(2256.85,1802.24) 2284.88,1774.21 U1.10@2310.51,1774.21
  Signal Layer 3 w8: 2210,1250 2210,1535 2230,1555 2230,1775.39 v2(2256.85,1802.24)
  Bottom Layer w7: U10.76@3260.87,161.85 3260.87,119.13 v2(3270,110)
PN2: R109.2 U10.109 | length 103.7
  Top Layer w7: R109.2@2783,410 v2@2805,410
  Bottom Layer w7: v2(2805.12,409.88) U10.109@2886.85,409.88
PN3: R110.2 U10.110 | length 137.7
  Top Layer w7: R110.2@2783,465 v2(2810,465)
  Bottom Layer w7: v2(2810,465) 2810,435 2819.37,425.63 U10.110@2886.85,425.63
PP5: R108.1 U10.106 | length 107
  Top Layer w7: R108.1@2783,355 v2(2810,355)
  Bottom Layer w7: v2(2810,355) 2817.64,362.64 U10.106@2886.85,362.64
RST_N: C119.1 R89.2 R99.2 U10.70 | length 126.8
  Top Layer w8: v2(3585,1670) R89.2@3585,1702
  Bottom Layer w7: v1@3331.77,76.77 3355.35,100.35 U10.70@3355.35,161.85
  other v1: 3330,78.54
SSN_BOOST: R109.1 U1.5 | length 143.3
  Top Layer w8: v2(2345,1920) 2345,1905 2395.16,1854.84 U1.5@2395.16,1819.49
  Top Layer w10: v2(2705,410) R109.1@2727,410
SSN_BUCK_1-2: R43.2 R110.1 | length 55.5
  Top Layer w10: v2(2705,465) R110.1@2727,465
  Top Layer w15: v2(1100,625) R43.2@1133.5,625
TI: D12.2 D14.2 EC1.9
TI+: C28.1 C29.1 C134.1 L9.1 R19.2 R21.2 R27.2 | length 1316.5
  Top Layer w10: C134.1@816.5,1280 v2(855,1280)
  Signal Layer 4 w50: v1(240,1205) 535,1205 610,1280 1200,1280 1265,1345 1265,1540
  other v1: 210,1205 210,1230 240,1230 1240,1520 1280,1520 1240,1545 1280,1545
TI_Fault: EC1.12 R122.1 | length 306.6
  Bottom Layer w20: EC1.12@-160.24,1412.99 -7.01,1412.99 0,1420 R122.1@143.5,1420
TI_FAULT_MICRO: R125.2 U10.6
TI_MICRO: D16.1 R90.1 R114.2 R118.2 U10.104 | length 295.3
  Top Layer w15: v1(1010,1560) 1030.53,1539.47 D16.1@1030.53,1505
  Bottom Layer w7: v2(2740,305) 2766.14,331.14 U10.104@2886.85,331.14
  Bottom Layer w15: R114.2@971.5,1560 v1(1010,1560) 1043.5,1560 R118.2@1045,1558.5
TI_NTC: C88.1 EC1.36 R143.1 | length 1088.5
  Top Layer w25: R143.1@821.5,150 v1(821.5,183.43) C88.1@821.5,216.85
  Signal Layer 4 w10: v1(510,150) 788.07,150 v1(821.5,183.43)
  Bottom Layer w25: EC1.36@-160.24,212.99 -47.99,212.99 15,150 v1(510,150)
TI_RBIN: C87.1 EC1.34 R142.1 | length 1120.5
  Signal Layer 4 w10: v1(260,365) 565,365 580,350 710,350 745,385 v1(851.02,385)
  Bottom Layer w20: C87.1@821.5,385 v1(851.02,385) R142.1@888.5,385
  Bottom Layer w25: EC1.34@-160.24,312.99 207.99,312.99 v1(260,365)
TIND_NTC: C126.1 R141.1 R143.2 U10.20 | length 1559.9
  Top Layer w10: v2(3320,885) C126.1@3320,905
  Top Layer w25: R143.2@758.5,150 R141.1@758.5,85 758.5,46.5 765,40 2010,40
  Bottom Layer w7: U10.20@3245.12,750 3245.12,837.72 3292.4,885 v2(3320,885)
VBST: C1.2 C5.1 C6.1 C7.1 C8.1 C9.1 C10.2 C11.1 C43.2 C47.1 C52.2 C59.1 D1.3 R3.2 R8.2 U2.5 U2.6 U2.11 U2.12 | length 103.4
  Top Layer w20: R8.2@2630,1401.5 2630,1440 2643.76,1453.76 R3.2@2643.76,1499.24
  other v1: 2095,455 2140,455 2195,455 2250,455 2120,495 2225,495 2175.61,495.68 2095,540 2140,540 2195,540 2250,540
  other v2: 1675,525 1695,525 1675,540 1695,540 1675,680 1700,680 1675,695 1700,695
VDD: C38.2 U1.31 | length 84.7
  Top Layer w10: U1.31@2499.49,1774.21 2528.82,1774.21 2542.55,1787.94 C38.2@2578.52,1787.94
Vin: C2.2 C3.2 C4.1 C19.2 C20.1 C21.1 C22.1 C23.1 C78.1 C79.1 C80.1 C92.1 C93.1 D21.2 L1.1 L3.1 L10.2 R5.2 R11.1 R68.2 U4.2 | length 1277.5
  Top Layer w10: R5.2@2546.85,1995.75 v2(2575,1995.75) 2618.35,1995.75 R11.1@2621.85,1992.24 2742.76,1992.24 2780,1955 R68.2@2780,1906.5 2808.5,1906.5 v1(2825,1890) 2850.31,1864.69 U4.2@2907.4,1864.69
  Signal Layer 4 w10: v2(1740.75,1995.75) v2(2575,1995.75)
  other v1: 2335,1190 2360,1190 2390,1190 2460,1190 2485,1190 2510,1190 1745,1650 1660,1700 1745,1720 1485,1725 1520,1725 1555,1725 1625,1725 1660,1725 1485,1785 1510,1785 1535,1785 1560,1785 1585,1785 1610,1785 1635,1785 1660,1785 1685,1785 1710,1784.53 1735,1784.53
WAKE: R97.1 R98.1 U10.64 | length 185.1
  Top Layer w7: R98.1@3580,211.5 3585,216.5 v1(3585,250) 3585,288.5 R97.1@3586.5,290
  Bottom Layer w7: U10.64@3493.15,220.91 3555.91,220.91 v1(3585,250)
pads on no net: EC1.13 EC1.14 EC1.21 EC1.22 EC1.25 EC1.29 EC1.30 EC1.31 FID1.1 FID2.1 FID3.1 H1.1 H2.1 H3.1 H4.1 H5.0 H6.0 H7.0 H8.0 H9.0 H10.0 H11.0 H12.0 LBL1.0 Q6.9@118.74,1700 Q6.9@124.65,1677.56 Q6.9@124.65,1722.44 Q6.9@147.68,1638.98 Q6.9@147.68,1700 Q6.9@147.68,1761.02 Q9.9@78.98,1052.32 Q9.9@117.56,1075.35 Q9.9@140,1052.32 Q9.9@140,1081.26 Q9.9@162.44,1075.35 Q9.9@201.02,1052.32 U1.13 U2.33@1480.2,610.59 U3.3 U3.8 U4.11@2995,1845 U5.13 U5.16 U5.21@3085,1255 U10.3 U10.11 U10.22 U10.27 U10.31 U10.32 U10.33 U10.34 U10.35 U10.36 U10.37 U10.38 U10.40 U10.41 U10.43 U10.46 U10.50 U10.60 U10.61 U10.62 U10.63 U10.65 U10.71 U10.72 U10.73 U10.74 U10.75 U10.78 U10.81 U10.82 U10.83 U10.84 U10.86 U10.91 U10.92 U10.93 U10.94 U10.102 U10.105 U10.107 U10.108 U10.111 U10.112 U10.120 U10.121 U10.124 U10.125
